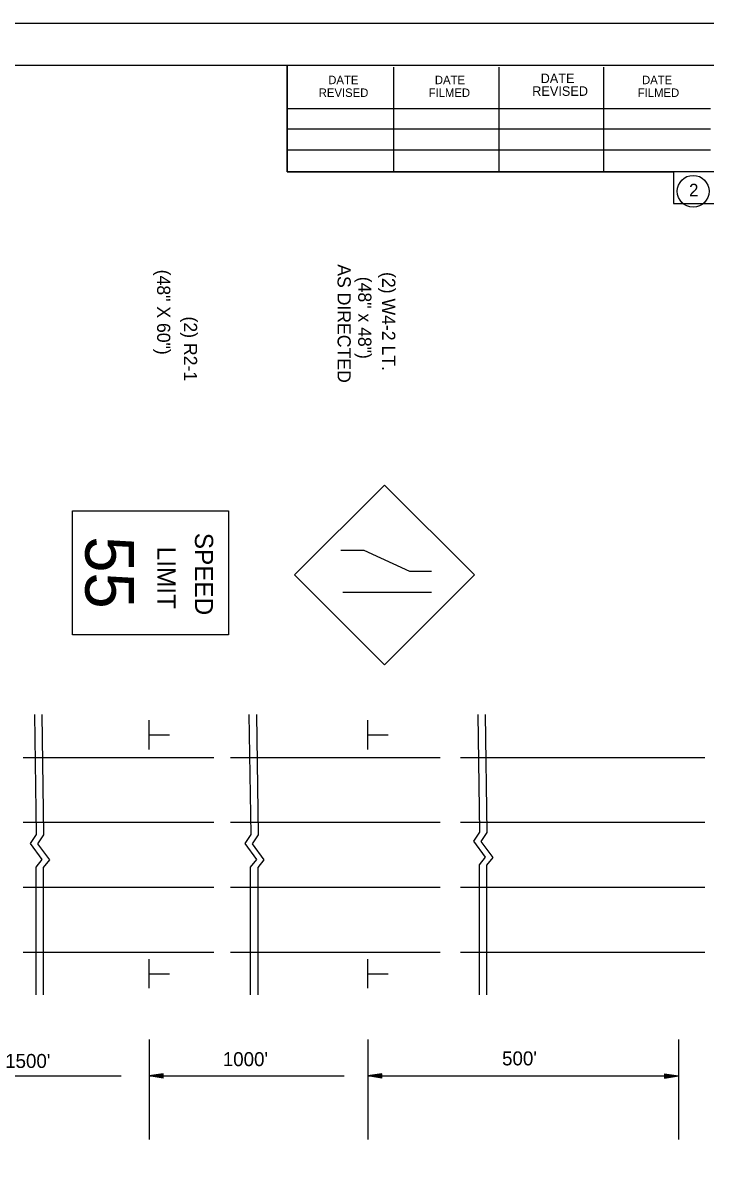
# Model space of a CAD drawing. Extents: x 1397271 to 1411271, y 376395 to 377888.
# Drawn here: x 1405825 to 1406267, y 377141 to 377888 of the extents above; entities that cross this region are included whole.
import ezdxf

# ---------------------------------------------------------------- set-up
doc = ezdxf.new("R2010")
doc.units = 0
for name, color, linetype in [('Default', 7, 'Continuous'), ('R_Border', 7, 'Continuous'), ('R_MOT', 7, 'Continuous'), ('R_No Plot', 7, 'Continuous')]:
    doc.layers.add(name, color=color, linetype=linetype)

msp = doc.modelspace()

# ---------------------------------------------------------------- linework, layer by layer
at = {"layer": 'Default'}
for p, q in [((1405824.58, 377412.4), (1405948.05, 377412.4)), ((1405958.74, 377412.4), (1406094.56, 377412.4)), ((1406107.59, 377412.4), (1406211.24, 377412.4)), ((1406211.24, 377412.4), (1406265.95, 377412.4)), ((1405824.58, 377370.37), (1405948.05, 377370.37)), ((1405958.74, 377370.37), (1406094.56, 377370.37)), ((1406107.59, 377370.37), (1406211.24, 377370.37)), ((1406211.24, 377370.37), (1406265.95, 377370.37)), ((1405824.58, 377328.34), (1405948.05, 377328.34)), ((1405958.74, 377328.34), (1406094.56, 377328.34)), ((1406107.59, 377328.34), (1406211.24, 377328.34)), ((1406211.24, 377328.34), (1406265.95, 377328.34)), ((1405824.58, 377286.3), (1405948.05, 377286.3)), ((1405958.74, 377286.3), (1406094.56, 377286.3)), ((1406107.59, 377286.3), (1406211.24, 377286.3)), ((1406211.24, 377286.3), (1406265.95, 377286.3)), ((1405906.2, 377229.73), (1405906.2, 377164.82)), ((1406047.68, 377229.73), (1406047.68, 377164.82)), ((1406248.78, 377229.73), (1406248.78, 377164.82)), ((1405761.88, 377206.06), (1405888.06, 377206.06)), ((1405915.27, 377207.42), (1405906.2, 377206.06)), ((1405906.2, 377206.06), (1406032.39, 377206.06)), ((1405915.27, 377204.7), (1405906.2, 377206.06)), ((1405915.27, 377207.19), (1405907.72, 377206.06)), ((1405915.27, 377204.92), (1405907.72, 377206.06)), ((1405915.27, 377206.96), (1405909.28, 377206.06)), ((1405915.27, 377205.15), (1405909.28, 377206.06)), ((1405915.27, 377206.73), (1405910.79, 377206.06)), ((1405915.27, 377205.38), (1405910.79, 377206.06)), ((1405915.27, 377206.5), (1405912.32, 377206.06)), ((1405915.27, 377205.62), (1405912.32, 377206.06)), ((1405915.27, 377206.27), (1405913.84, 377206.06)), ((1405915.27, 377205.84), (1405913.84, 377206.06)), ((1405915.27, 377204.7), (1405915.27, 377207.42)), ((1406056.75, 377207.42), (1406047.68, 377206.06)), ((1406047.68, 377206.06), (1406248.78, 377206.06)), ((1406056.75, 377204.7), (1406047.68, 377206.06)), ((1406056.75, 377207.19), (1406049.19, 377206.06)), ((1406056.75, 377204.92), (1406049.19, 377206.06)), ((1406056.75, 377206.96), (1406050.75, 377206.06)), ((1406056.75, 377205.15), (1406050.75, 377206.06)), ((1406056.75, 377206.73), (1406052.26, 377206.06)), ((1406056.75, 377205.38), (1406052.26, 377206.06)), ((1406056.75, 377206.5), (1406053.8, 377206.06)), ((1406056.75, 377205.62), (1406053.8, 377206.06)), ((1406056.75, 377206.27), (1406055.31, 377206.06)), ((1406056.75, 377205.84), (1406055.31, 377206.06)), ((1406056.75, 377204.7), (1406056.75, 377207.42)), ((1406239.72, 377207.42), (1406248.78, 377206.06)), ((1406239.72, 377207.42), (1406239.72, 377204.7)), ((1406239.72, 377207.19), (1406247.27, 377206.06)), ((1406239.72, 377206.96), (1406245.71, 377206.06)), ((1406239.72, 377206.73), (1406244.2, 377206.06)), ((1406239.72, 377206.5), (1406242.66, 377206.06)), ((1406239.72, 377206.27), (1406241.15, 377206.06)), ((1406239.72, 377204.7), (1406248.78, 377206.06)), ((1406239.72, 377205.61), (1406242.66, 377206.06)), ((1406239.72, 377205.15), (1406245.71, 377206.06)), ((1406239.72, 377204.92), (1406247.27, 377206.06)), ((1406239.72, 377205.38), (1406244.2, 377206.06)), ((1406239.72, 377205.84), (1406241.15, 377206.06))]:
    msp.add_line(p, q, dxfattribs=at)
for points in [[(1405831.81, 377440.23), (1405832.99, 377362.48), (1405829.07, 377356.64), (1405836.71, 377346.17), (1405832.69, 377341.34), (1405832.67, 377258.48)], [(1405836.64, 377440.23), (1405837.82, 377362.27), (1405833.89, 377356.44), (1405841.54, 377345.97), (1405837.52, 377341.14), (1405837.5, 377258.48)], [(1405970.74, 377440.23), (1405971.92, 377362.48), (1405967.99, 377356.64), (1405975.64, 377346.17), (1405971.62, 377341.34), (1405971.6, 377258.48)], [(1405975.56, 377440.23), (1405976.75, 377362.27), (1405972.82, 377356.44), (1405980.47, 377345.97), (1405976.45, 377341.14), (1405976.43, 377258.48)], [(1406118.85, 377440.23), (1406120.01, 377364), (1406116.08, 377358.16), (1406123.73, 377347.7), (1406119.7, 377342.86), (1406119.68, 377258.48)], [(1406123.67, 377440.23), (1406124.83, 377363.8), (1406120.91, 377357.96), (1406128.56, 377347.49), (1406124.53, 377342.66), (1406124.52, 377258.48)]]:
    msp.add_lwpolyline(points, dxfattribs=at)
at = {"layer": 'R_Border'}
for p, q in [((1404358, 377860.72), (1406571.3, 377860.72)), ((1405995.47, 377791.56), (1405995.47, 377860.72)), ((1406064.49, 377791.56), (1406064.49, 377859.32)), ((1406132.81, 377791.56), (1406132.81, 377859.32)), ((1406200.57, 377791.56), (1406200.57, 377859.32)), ((1405995.47, 377832.58), (1406269.59, 377832.58)), ((1405995.47, 377819.56), (1406269.59, 377819.56)), ((1405995.47, 377791.56), (1405995.47, 377805.98)), ((1405995.47, 377805.98), (1406269.59, 377805.98)), ((1406571.3, 377791.56), (1405995.47, 377791.56))]:
    msp.add_line(p, q, dxfattribs=at)
msp.add_circle((1406258.3, 377779.07), 10.27, dxfattribs=at)
at = {"layer": 'R_MOT'}
for p, q in [((1406000.28, 377530.51), (1406058.54, 377588.77)), ((1406058.54, 377588.77), (1406116.8, 377530.51)), ((1406030.32, 377546.48), (1406045.14, 377546.48)), ((1406045.14, 377546.48), (1406074.75, 377532.89)), ((1406058.54, 377472.26), (1406000.28, 377530.51)), ((1406116.8, 377530.51), (1406058.54, 377472.26)), ((1406074.75, 377532.89), (1406088.86, 377532.89)), ((1406031.55, 377519.31), (1406088.86, 377519.31)), ((1405906.2, 377417.59), (1405906.2, 377436.5)), ((1406047.68, 377417.59), (1406047.68, 377436.5)), ((1405906.48, 377427), (1405919.39, 377427)), ((1406047.96, 377427), (1406060.87, 377427)), ((1405906.2, 377262.83), (1405906.2, 377281.74)), ((1406047.68, 377262.83), (1406047.68, 377281.74)), ((1405906.48, 377272.24), (1405919.39, 377272.24)), ((1406047.96, 377272.24), (1406060.87, 377272.24))]:
    msp.add_line(p, q, dxfattribs=at)
msp.add_lwpolyline([(1405957.55, 377491.84), (1405856.44, 377491.84), (1405856.44, 377572.07), (1405957.55, 377572.07)], close=True, dxfattribs=at)
at = {"layer": 'R_No Plot'}
msp.add_line((1404271.19, 377887.98), (1406604.57, 377887.98), dxfattribs=at)
for points in [[(1404271.14, 377887.98), (1406604.57, 377887.98), (1406604.57, 376394.59), (1404271.14, 376394.59)], [(1405995.47, 377860.72), (1405995.47, 377791.56), (1406245.6, 377791.56), (1406245.6, 377771.12), (1406408, 377771.12), (1406408, 377600.79), (1406571.3, 377600.79), (1406571.3, 376422.47), (1404358, 376422.47), (1404358, 377860.72)]]:
    msp.add_lwpolyline(points, close=True, dxfattribs=at)

# ---------------------------------------------------------------- texts
at = {"layer": 'Default'}
for s, p in [("1500'", (1405812.91, 377211.22)), ("1000'", (1405953.8, 377212.39)), ("500'", (1406134.6, 377212.9))]:
    msp.add_text(s, height=9.067, dxfattribs=at).set_placement(p)
at = {"layer": 'R_Border'}
for s, height, p in [('DATE', 5.474, (1406022.07, 377848.4)), ('DATE', 5.474, (1406091.09, 377848.4)), ('DATE', 6.155, (1406159.55, 377849.1)), ('DATE', 5.474, (1406225.21, 377848.4)), ('REVISED', 5.474, (1406015.91, 377840.14)), ('FILMED', 5.474, (1406087.03, 377840.14)), ('REVISED', 6.155, (1406154.09, 377840.84)), ('FILMED', 5.474, (1406222.41, 377840.14)), ('2', 8.21, (1406255.62, 377775.66))]:
    msp.add_text(s, height=height, rotation=360, dxfattribs=at).set_placement(p)
at = {"layer": 'R_MOT'}
for s, height, p in [('AS DIRECTED ', 8.5402, (1406028.08, 377731.76)), ('(48" X 60")', 8.5402, (1405911.27, 377728.25)), ('(2) W4-2 LT.', 8.5402, (1406056.94, 377726.72)), ('(48" x 48")', 8.5402, (1406041.45, 377723.67)), ('(2) R2-1', 8.54, (1405928.65, 377697.93)), ('55', 31.526, (1405864.81, 377555.61)), ('SPEED', 11.763, (1405935.78, 377557.8)), ('LIMIT', 11.763, (1405911.47, 377548.78))]:
    msp.add_text(s, height=height, rotation=270, dxfattribs=at).set_placement(p)

doc.saveas('drawing.dxf')
